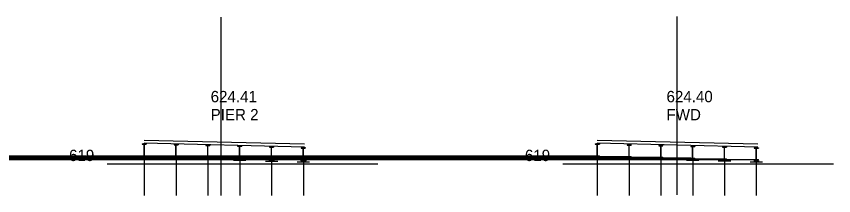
# Model space of a CAD drawing. Extents: x 2376379 to 2383101, y 559608 to 561720.
# Drawn here: x 2377498.6 to 2377701, y 560758 to 560802.2 of the extents above; entities that cross this region are included whole.
import ezdxf

# ---------------------------------------------------------------- set-up
doc = ezdxf.new("R2010")
doc.units = 0
doc.layers.add('DR_X_Ditch', color=7, linetype='Continuous')
doc.layers.add('SV_X_Toe_of_Slope', color=7, linetype='Continuous')

msp = doc.modelspace()

# ---------------------------------------------------------------- linework, layer by layer
at = {"layer": 'DR_X_Ditch'}
for p, q in [((2377529.77, 560770.73), (2377530.77, 560770.73)), ((2377529.77, 560770.73), (2377529.77, 560770.65)), ((2377529.77, 560770.73), (2377530.77, 560770.73)), ((2377529.77, 560770.65), (2377530.77, 560770.65)), ((2377529.84, 560770.77), (2377530.71, 560770.77)), ((2377529.84, 560770.77), (2377529.84, 560770.73)), ((2377530.25, 560767.82), (2377530.25, 560770.65)), ((2377530.3, 560767.82), (2377530.3, 560770.65)), ((2377530.71, 560770.77), (2377530.71, 560770.73)), ((2377530.77, 560770.73), (2377530.77, 560770.65)), ((2377537.65, 560770.56), (2377538.65, 560770.56)), ((2377537.65, 560770.56), (2377537.65, 560770.48)), ((2377537.65, 560770.56), (2377538.65, 560770.56)), ((2377537.65, 560770.48), (2377538.65, 560770.48)), ((2377537.72, 560770.6), (2377538.59, 560770.6)), ((2377537.72, 560770.6), (2377537.72, 560770.56)), ((2377538.13, 560767.65), (2377538.13, 560770.48)), ((2377538.18, 560767.65), (2377538.18, 560770.48)), ((2377538.59, 560770.6), (2377538.59, 560770.56)), ((2377538.65, 560770.56), (2377538.65, 560770.48)), ((2377545.52, 560770.38), (2377546.52, 560770.38)), ((2377545.52, 560770.38), (2377545.52, 560770.3)), ((2377545.52, 560770.38), (2377546.52, 560770.38)), ((2377545.52, 560770.3), (2377546.52, 560770.3)), ((2377545.59, 560770.42), (2377546.46, 560770.42)), ((2377545.59, 560770.42), (2377545.59, 560770.38)), ((2377546, 560767.47), (2377546, 560770.3)), ((2377546.05, 560767.47), (2377546.05, 560770.3)), ((2377546.46, 560770.42), (2377546.46, 560770.38)), ((2377546.52, 560770.38), (2377546.52, 560770.3)), ((2377553.4, 560770.22), (2377554.4, 560770.22)), ((2377553.4, 560770.22), (2377553.4, 560770.14)), ((2377553.4, 560770.22), (2377554.4, 560770.22)), ((2377553.4, 560770.14), (2377554.4, 560770.14)), ((2377553.47, 560770.26), (2377554.34, 560770.26)), ((2377553.47, 560770.26), (2377553.47, 560770.22)), ((2377553.88, 560767.31), (2377553.88, 560770.14)), ((2377553.93, 560767.31), (2377553.93, 560770.14)), ((2377554.34, 560770.26), (2377554.34, 560770.22)), ((2377554.4, 560770.22), (2377554.4, 560770.14)), ((2377561.27, 560769.98), (2377562.27, 560769.98)), ((2377561.27, 560769.98), (2377561.27, 560769.9)), ((2377561.27, 560769.98), (2377562.27, 560769.98)), ((2377561.27, 560769.9), (2377562.27, 560769.9)), ((2377561.34, 560770.02), (2377562.21, 560770.02)), ((2377561.34, 560770.02), (2377561.34, 560769.98)), ((2377561.75, 560767.07), (2377561.75, 560769.9)), ((2377561.8, 560767.07), (2377561.8, 560769.9)), ((2377562.21, 560770.02), (2377562.21, 560769.98)), ((2377562.27, 560769.98), (2377562.27, 560769.9)), ((2377569.15, 560769.77), (2377570.15, 560769.77)), ((2377569.15, 560769.77), (2377569.15, 560769.69)), ((2377569.15, 560769.77), (2377570.15, 560769.77)), ((2377569.15, 560769.69), (2377570.15, 560769.69)), ((2377569.22, 560769.81), (2377570.09, 560769.81)), ((2377569.22, 560769.81), (2377569.22, 560769.77)), ((2377569.63, 560766.86), (2377569.63, 560769.69)), ((2377569.68, 560766.86), (2377569.68, 560769.69)), ((2377570.09, 560769.81), (2377570.09, 560769.77)), ((2377570.15, 560769.77), (2377570.15, 560769.69)), ((2377641.96, 560770.74), (2377642.96, 560770.74)), ((2377641.96, 560770.74), (2377641.96, 560770.65)), ((2377641.96, 560770.65), (2377642.96, 560770.65)), ((2377642.44, 560767.82), (2377642.44, 560770.65)), ((2377642.49, 560767.82), (2377642.49, 560770.65)), ((2377642.96, 560770.74), (2377642.96, 560770.65)), ((2377649.83, 560770.53), (2377650.83, 560770.53)), ((2377649.83, 560770.53), (2377649.83, 560770.44)), ((2377649.83, 560770.44), (2377650.83, 560770.44)), ((2377650.31, 560767.61), (2377650.31, 560770.44)), ((2377650.36, 560767.61), (2377650.36, 560770.44)), ((2377650.83, 560770.53), (2377650.83, 560770.44)), ((2377657.7, 560770.37), (2377658.7, 560770.37)), ((2377657.7, 560770.37), (2377657.7, 560770.28)), ((2377657.7, 560770.28), (2377658.7, 560770.28)), ((2377658.18, 560767.45), (2377658.18, 560770.28)), ((2377658.23, 560767.45), (2377658.23, 560770.28)), ((2377658.7, 560770.37), (2377658.7, 560770.28)), ((2377665.58, 560770.16), (2377666.58, 560770.16)), ((2377665.58, 560770.16), (2377665.58, 560770.07)), ((2377665.58, 560770.07), (2377666.58, 560770.07)), ((2377666.06, 560767.24), (2377666.06, 560770.07)), ((2377666.11, 560767.24), (2377666.11, 560770.07)), ((2377666.58, 560770.16), (2377666.58, 560770.07)), ((2377673.45, 560770), (2377674.45, 560770)), ((2377673.45, 560770), (2377673.45, 560769.91)), ((2377673.45, 560769.91), (2377674.45, 560769.91)), ((2377673.93, 560767.08), (2377673.93, 560769.91)), ((2377673.98, 560767.08), (2377673.98, 560769.91)), ((2377674.45, 560770), (2377674.45, 560769.91)), ((2377681.33, 560769.8), (2377682.33, 560769.8)), ((2377681.33, 560769.8), (2377681.33, 560769.71)), ((2377681.33, 560769.71), (2377682.33, 560769.71)), ((2377681.81, 560766.88), (2377681.81, 560769.71)), ((2377681.86, 560766.88), (2377681.86, 560769.71)), ((2377682.33, 560769.8), (2377682.33, 560769.71)), ((2377529.71, 560767.73), (2377529.77, 560767.73)), ((2377529.71, 560767.73), (2377529.71, 560767.65)), ((2377529.71, 560767.69), (2377530.84, 560767.69)), ((2377529.71, 560767.65), (2377530.84, 560767.65)), ((2377529.77, 560767.82), (2377530.77, 560767.82)), ((2377529.77, 560767.82), (2377529.77, 560767.73)), ((2377529.77, 560767.73), (2377530.77, 560767.73)), ((2377530.77, 560767.73), (2377530.77, 560767.82)), ((2377530.77, 560767.73), (2377530.84, 560767.73)), ((2377530.84, 560767.73), (2377530.84, 560767.65)), ((2377537.59, 560767.56), (2377537.65, 560767.56)), ((2377537.59, 560767.56), (2377537.59, 560767.48)), ((2377537.59, 560767.52), (2377538.72, 560767.52)), ((2377537.59, 560767.48), (2377538.72, 560767.48)), ((2377537.65, 560767.65), (2377538.65, 560767.65)), ((2377537.65, 560767.65), (2377537.65, 560767.56)), ((2377537.65, 560767.56), (2377538.65, 560767.56)), ((2377538.65, 560767.56), (2377538.65, 560767.65)), ((2377538.65, 560767.56), (2377538.72, 560767.56)), ((2377538.72, 560767.56), (2377538.72, 560767.48)), ((2377545.46, 560767.38), (2377545.52, 560767.38)), ((2377545.46, 560767.38), (2377545.46, 560767.3)), ((2377545.46, 560767.34), (2377546.59, 560767.34)), ((2377545.46, 560767.3), (2377546.59, 560767.3)), ((2377545.52, 560767.47), (2377546.52, 560767.47)), ((2377545.52, 560767.47), (2377545.52, 560767.38)), ((2377545.52, 560767.38), (2377546.52, 560767.38)), ((2377546.52, 560767.38), (2377546.52, 560767.47)), ((2377546.52, 560767.38), (2377546.59, 560767.38)), ((2377546.59, 560767.38), (2377546.59, 560767.3)), ((2377553.34, 560767.22), (2377553.4, 560767.22)), ((2377553.34, 560767.22), (2377553.34, 560767.14)), ((2377553.34, 560767.18), (2377554.47, 560767.18)), ((2377553.34, 560767.14), (2377554.47, 560767.14)), ((2377553.4, 560767.31), (2377554.4, 560767.31)), ((2377553.4, 560767.31), (2377553.4, 560767.22)), ((2377553.4, 560767.22), (2377554.4, 560767.22)), ((2377554.4, 560767.22), (2377554.4, 560767.31)), ((2377554.4, 560767.22), (2377554.47, 560767.22)), ((2377554.47, 560767.22), (2377554.47, 560767.14)), ((2377561.21, 560766.98), (2377561.27, 560766.98)), ((2377561.21, 560766.98), (2377561.21, 560766.9)), ((2377561.21, 560766.94), (2377562.34, 560766.94)), ((2377561.21, 560766.9), (2377562.34, 560766.9)), ((2377561.27, 560767.07), (2377562.27, 560767.07)), ((2377561.27, 560767.07), (2377561.27, 560766.98)), ((2377561.27, 560766.98), (2377562.27, 560766.98)), ((2377562.27, 560766.98), (2377562.27, 560767.07)), ((2377562.27, 560766.98), (2377562.34, 560766.98)), ((2377562.34, 560766.98), (2377562.34, 560766.9)), ((2377641.96, 560767.82), (2377642.96, 560767.82)), ((2377641.96, 560767.82), (2377641.96, 560767.74)), ((2377641.96, 560767.74), (2377642.96, 560767.74)), ((2377642.96, 560767.74), (2377642.96, 560767.82)), ((2377649.83, 560767.61), (2377650.83, 560767.61)), ((2377649.83, 560767.61), (2377649.83, 560767.53)), ((2377649.83, 560767.53), (2377650.83, 560767.53)), ((2377650.83, 560767.53), (2377650.83, 560767.61)), ((2377657.7, 560767.45), (2377658.7, 560767.45)), ((2377657.7, 560767.45), (2377657.7, 560767.37)), ((2377657.7, 560767.37), (2377658.7, 560767.37)), ((2377658.7, 560767.37), (2377658.7, 560767.45)), ((2377665.58, 560767.24), (2377666.58, 560767.24)), ((2377665.58, 560767.24), (2377665.58, 560767.16)), ((2377665.58, 560767.16), (2377666.58, 560767.16)), ((2377666.58, 560767.16), (2377666.58, 560767.24)), ((2377673.45, 560767.08), (2377674.45, 560767.08)), ((2377673.45, 560767.08), (2377673.45, 560767)), ((2377673.45, 560767), (2377674.45, 560767)), ((2377674.45, 560767), (2377674.45, 560767.08)), ((2377681.33, 560766.88), (2377682.33, 560766.88)), ((2377681.33, 560766.88), (2377681.33, 560766.8)), ((2377682.33, 560766.8), (2377682.33, 560766.88)), ((2377569.09, 560766.77), (2377569.15, 560766.77)), ((2377569.09, 560766.77), (2377569.09, 560766.69)), ((2377569.09, 560766.73), (2377570.22, 560766.73)), ((2377569.09, 560766.69), (2377570.22, 560766.69)), ((2377569.15, 560766.86), (2377570.15, 560766.86)), ((2377569.15, 560766.86), (2377569.15, 560766.77)), ((2377569.15, 560766.77), (2377570.15, 560766.77)), ((2377570.15, 560766.77), (2377570.15, 560766.86)), ((2377570.15, 560766.77), (2377570.22, 560766.77)), ((2377570.22, 560766.77), (2377570.22, 560766.69)), ((2377681.33, 560766.8), (2377682.33, 560766.8))]:
    msp.add_line(p, q, dxfattribs=at)
at = {"layer": 'SV_X_Toe_of_Slope'}
for p, q in [((2377549.26, 560802.07), (2377549.26, 560757.96)), ((2377662.13, 560802.23), (2377662.13, 560758.12)), ((2377530.27, 560771.67), (2377569.99, 560770.72)), ((2377530.27, 560770.96), (2377569.99, 560770.01)), ((2377530.27, 560770.77), (2377530.27, 560770.94)), ((2377642.46, 560771.67), (2377682.17, 560770.72)), ((2377642.46, 560770.96), (2377682.17, 560770.01)), ((2377538.15, 560770.6), (2377538.15, 560770.77)), ((2377546.02, 560770.42), (2377546.02, 560770.59)), ((2377553.9, 560770.26), (2377553.9, 560770.43)), ((2377561.77, 560770.02), (2377561.77, 560770.19)), ((2377569.65, 560769.81), (2377569.65, 560769.98)), ((2377642.46, 560770.74), (2377642.46, 560770.9)), ((2377650.33, 560770.53), (2377650.33, 560770.69)), ((2377658.2, 560770.37), (2377658.2, 560770.53)), ((2377666.08, 560770.16), (2377666.08, 560770.32)), ((2377673.95, 560770), (2377673.95, 560770.16)), ((2377681.83, 560769.8), (2377681.83, 560769.96)), ((2377641.92, 560767.73), (2377275.85, 560767.73)), ((2377649.79, 560767.56), (2377283.73, 560767.56)), ((2377657.66, 560767.38), (2377291.6, 560767.38)), ((2377665.58, 560767.22), (2377299.48, 560767.22)), ((2377673.41, 560766.98), (2377307.35, 560766.98)), ((2377528.76, 560767.23), (2377531.83, 560767.23)), ((2377529.63, 560767.65), (2377530.92, 560767.65)), ((2377529.63, 560767.65), (2377529.63, 560767.52)), ((2377529.63, 560767.52), (2377530.92, 560767.52)), ((2377529.75, 560767.52), (2377529.75, 560767.23)), ((2377530.29, 560767.23), (2377530.29, 560757.96)), ((2377530.84, 560767.52), (2377530.84, 560767.23)), ((2377530.92, 560767.65), (2377530.92, 560767.52)), ((2377536.64, 560767.06), (2377539.71, 560767.06)), ((2377537.51, 560767.48), (2377538.8, 560767.48)), ((2377537.51, 560767.48), (2377537.51, 560767.35)), ((2377537.51, 560767.35), (2377538.8, 560767.35)), ((2377537.63, 560767.35), (2377537.63, 560767.06)), ((2377538.17, 560767.06), (2377538.17, 560757.96)), ((2377538.72, 560767.35), (2377538.72, 560767.06)), ((2377538.8, 560767.48), (2377538.8, 560767.35)), ((2377544.51, 560766.88), (2377547.58, 560766.88)), ((2377545.38, 560767.3), (2377546.67, 560767.3)), ((2377545.38, 560767.3), (2377545.38, 560767.17)), ((2377545.38, 560767.17), (2377546.67, 560767.17)), ((2377545.5, 560767.17), (2377545.5, 560766.88)), ((2377546.04, 560766.88), (2377546.04, 560757.96)), ((2377546.59, 560767.17), (2377546.59, 560766.88)), ((2377546.67, 560767.3), (2377546.67, 560767.17)), ((2377553.26, 560767.14), (2377554.55, 560767.14)), ((2377553.26, 560767.14), (2377553.26, 560767.01)), ((2377553.26, 560767.01), (2377554.55, 560767.01)), ((2377553.38, 560767.01), (2377553.38, 560766.72)), ((2377554.47, 560767.01), (2377554.47, 560766.72)), ((2377554.55, 560767.14), (2377554.55, 560767.01)), ((2377561.13, 560766.9), (2377562.42, 560766.9)), ((2377561.13, 560766.9), (2377561.13, 560766.77)), ((2377562.42, 560766.9), (2377562.42, 560766.77)), ((2377640.93, 560767.26), (2377644, 560767.26)), ((2377641.92, 560767.74), (2377643, 560767.74)), ((2377641.92, 560767.74), (2377643, 560767.74)), ((2377641.92, 560767.61), (2377641.92, 560767.49)), ((2377641.92, 560767.49), (2377643, 560767.49)), ((2377641.96, 560767.49), (2377641.96, 560767.26)), ((2377642.46, 560767.26), (2377642.46, 560757.96)), ((2377642.96, 560767.49), (2377642.96, 560767.26)), ((2377643, 560767.61), (2377643, 560767.49)), ((2377648.8, 560767.05), (2377651.87, 560767.05)), ((2377649.79, 560767.53), (2377650.87, 560767.53)), ((2377649.79, 560767.53), (2377650.87, 560767.53)), ((2377649.79, 560767.4), (2377649.79, 560767.28)), ((2377649.79, 560767.28), (2377650.87, 560767.28)), ((2377649.83, 560767.28), (2377649.83, 560767.05)), ((2377650.33, 560767.05), (2377650.33, 560757.96)), ((2377650.83, 560767.28), (2377650.83, 560767.05)), ((2377650.87, 560767.4), (2377650.87, 560767.28)), ((2377656.67, 560766.89), (2377659.74, 560766.89)), ((2377657.66, 560767.37), (2377658.74, 560767.37)), ((2377657.66, 560767.37), (2377658.74, 560767.37)), ((2377657.66, 560767.24), (2377657.66, 560767.12)), ((2377657.66, 560767.12), (2377658.74, 560767.12)), ((2377657.7, 560767.12), (2377657.7, 560766.89)), ((2377658.2, 560766.89), (2377658.2, 560757.96)), ((2377658.7, 560767.12), (2377658.7, 560766.89)), ((2377658.74, 560767.24), (2377658.74, 560767.12)), ((2377665.54, 560767.16), (2377666.62, 560767.16)), ((2377665.54, 560767.16), (2377666.62, 560767.16)), ((2377665.54, 560767.03), (2377665.54, 560766.91)), ((2377665.54, 560766.91), (2377666.62, 560766.91)), ((2377665.58, 560766.91), (2377665.58, 560766.68)), ((2377666.58, 560766.91), (2377666.58, 560766.68)), ((2377666.62, 560767.03), (2377666.62, 560766.91)), ((2377673.41, 560767), (2377674.49, 560767)), ((2377673.41, 560767), (2377674.49, 560767)), ((2377681.29, 560766.77), (2377315.23, 560766.77)), ((2377521.09, 560765.8), (2377588.11, 560765.8)), ((2377552.39, 560766.72), (2377555.46, 560766.72)), ((2377553.92, 560766.72), (2377553.92, 560757.96)), ((2377560.26, 560766.48), (2377563.33, 560766.48)), ((2377561.13, 560766.77), (2377562.42, 560766.77)), ((2377561.25, 560766.77), (2377561.25, 560766.48)), ((2377561.79, 560766.48), (2377561.79, 560757.96)), ((2377562.34, 560766.77), (2377562.34, 560766.48)), ((2377568.14, 560766.27), (2377571.21, 560766.27)), ((2377569.01, 560766.69), (2377570.3, 560766.69)), ((2377569.01, 560766.69), (2377569.01, 560766.56)), ((2377569.01, 560766.56), (2377570.3, 560766.56)), ((2377569.13, 560766.56), (2377569.13, 560766.27)), ((2377569.67, 560766.27), (2377569.67, 560757.96)), ((2377570.22, 560766.56), (2377570.22, 560766.27)), ((2377570.3, 560766.69), (2377570.3, 560766.56)), ((2377633.95, 560765.8), (2377700.98, 560765.8)), ((2377664.55, 560766.68), (2377667.62, 560766.68)), ((2377666.08, 560766.68), (2377666.08, 560757.96)), ((2377672.42, 560766.52), (2377675.49, 560766.52)), ((2377673.41, 560766.87), (2377673.41, 560766.75)), ((2377673.41, 560766.75), (2377674.49, 560766.75)), ((2377673.45, 560766.75), (2377673.45, 560766.52)), ((2377673.95, 560766.52), (2377673.95, 560757.96)), ((2377674.45, 560766.75), (2377674.45, 560766.52)), ((2377674.49, 560766.87), (2377674.49, 560766.75)), ((2377680.3, 560766.32), (2377683.37, 560766.32)), ((2377681.29, 560766.8), (2377682.37, 560766.8)), ((2377681.29, 560766.8), (2377682.37, 560766.8)), ((2377681.29, 560766.67), (2377681.29, 560766.55)), ((2377681.29, 560766.55), (2377682.37, 560766.55)), ((2377681.33, 560766.55), (2377681.33, 560766.32)), ((2377681.83, 560766.32), (2377681.83, 560757.96)), ((2377682.33, 560766.55), (2377682.33, 560766.32)), ((2377682.37, 560766.67), (2377682.37, 560766.55))]:
    msp.add_line(p, q, dxfattribs=at)

# ---------------------------------------------------------------- texts
for s, p in [('624.41', (2377546.72, 560781.02)), ('624.40', (2377659.59, 560781.02)), ('PIER 2', (2377546.72, 560776.56)), ('FWD', (2377659.59, 560776.56)), ('619', (2377511.66, 560766.49)), ('619', (2377624.53, 560766.49))]:
    msp.add_text(s, height=2.8, dxfattribs=at).set_placement(p)

doc.saveas('drawing.dxf')
